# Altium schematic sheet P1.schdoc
size 297 x 209 mm; Symbol: Drawing-Symbol_A4; @Project Name: Assisant vocal; @Page Count: 1; @Update Date: 2026-05-29; @Create Date: 2026-02-14; @Schematic Name: Dessous; @Page No: 1; @Page Name: P1; Company: EasyEDA.com; Version: V1.0; Page Size: A4; @Create Time: 20:23:05; @Update Time: 12:29:57; Border: 1; Width: 1170; Height: 825; Region Start: 1; X Region Count: 6; Y Region Count: 4; Blade Width: 10; Title Block Position: 3; @Board Name: Dessous; Device: Drawing-Symbol_A4
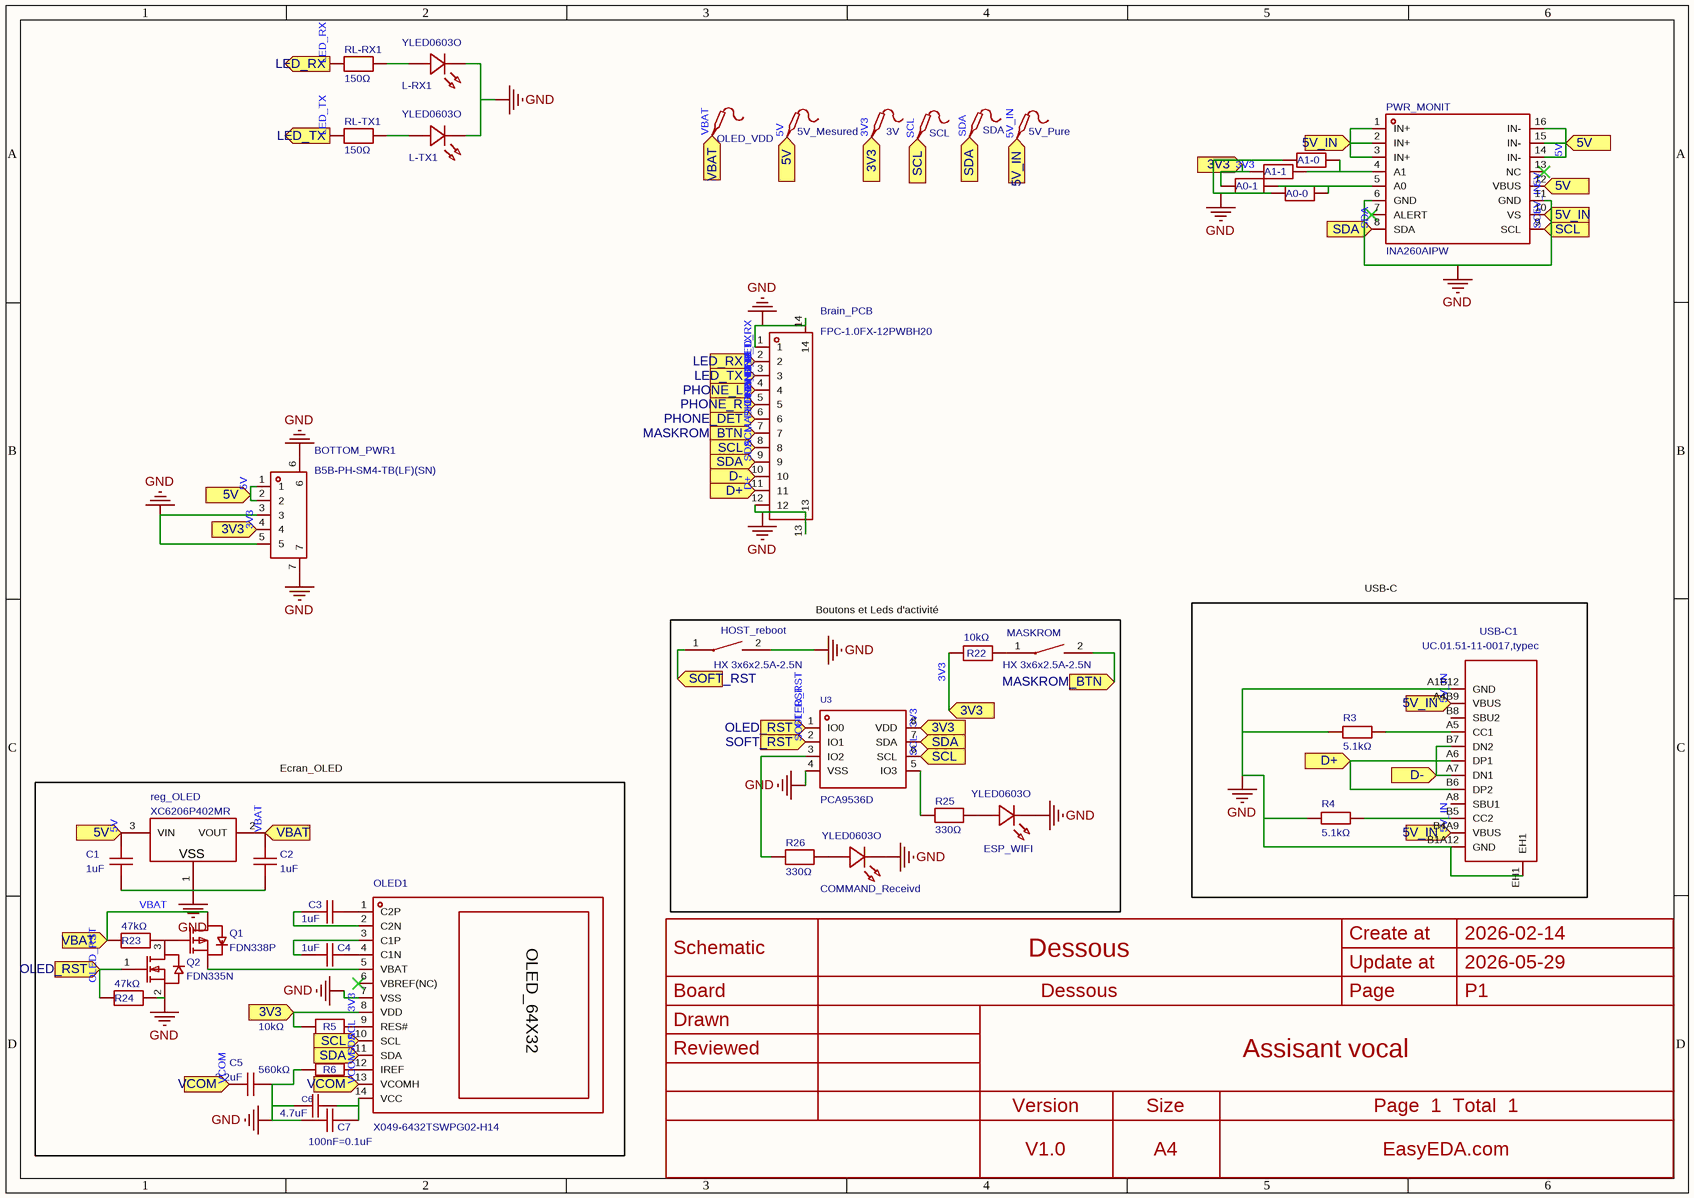
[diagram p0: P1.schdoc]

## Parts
3V  (no value)  [Test-Point-0.5mm]
5V_Mesured  (no value)  [Test-Point-0.5mm]
5V_Pure  (no value)  [Test-Point-0.5mm]
A0-0  0Ω  [R0402]  (value not drawn)
A0-1  0Ω  [R0402]  (value not drawn)
A1-0  0Ω  [R0402]  (value not drawn)
A1-1  0Ω  [R0402]  (value not drawn)
BOTTOM_PWR1  B5B-PH-SM4-TB(LF)(SN)  [CONN-SMD_5P-P2.00_B6B-PH-SM4-TB-LF-SN]
Brain_PCB  FPC-1.0FX-12PWBH20  [FPC-SMD_12P-P1.00_XUNPU_FPC-1.0FX-12PWBH20]
C1  1uF  [C0603]
C2  1uF  [C0603]
C3  1uF  [C0603]
C4  1uF  [C0603]
C5  2.2uF  [C0603]
C6  4.7uF  [C0603]
C7  100nF=0.1uF  [C0603]
COMMAND_Receivd  YLED0603O  [LED0603-FD]
ESP_WIFI  YLED0603O  [LED0603-FD]
HOST_reboot  HX 3x6x2.5A-2.5N  [SW-SMD_HX-TS-1101-C-W]
L-RX1  YLED0603O  [LED0603-FD]
L-TX1  YLED0603O  [LED0603-FD]
MASKROM  HX 3x6x2.5A-2.5N  [SW-SMD_HX-TS-1101-C-W]
OLED1  X049-6432TSWPG02-H14  [OLED-SMD_X049-6432TSWPG02-H14]
OLED_VDD  (no value)  [Test-Point-0.5mm]
PWR_MONIT  INA260AIPW  [TSSOP-16_L5.0-W4.4-P0.65-LS6.4-BL]
Q1  FDN338P  [SOT-23-3_L2.9-W1.3-P1.90-LS2.4-BR]
Q2  FDN335N  [SOT-23-3_L3.0-W1.7-P0.95-LS2.9-BR]
R3  5.1kΩ  [R0603_1]
R4  5.1kΩ  [R0603_1]
R5  10kΩ  [R0603]
R6  560kΩ  [R0603]
R22  10kΩ  [R0603]
R23  47kΩ  [R0603]
R24  47kΩ  [R0603]
R25  330Ω  [R0603]
R26  330Ω  [R0603]
reg_OLED  XC6206P402MR  [SOT-23-3_L2.9-W1.6-P1.90-LS2.8-BR]
RL-RX1  150Ω  [R0603]
RL-TX1  150Ω  [R0603]
SCL  (no value)  [Test-Point-0.5mm]
SDA  (no value)  [Test-Point-0.5mm]
U3  PCA9536D  [SOIC-8_L4.9-W3.9-P1.27-LS6.0-BL]
USB-C1  UC.01.51-11-0017,typec  [TYPE-C-SMD_UC.01.51-11-0017]

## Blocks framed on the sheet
Boutons et Leds d'activité: COMMAND_Receivd ESP_WIFI HOST_reboot MASKROM R22 R25 R26 U3
USB-C: R3 R4 USB-C1
Ecran_OLED: C1-C7 OLED1 Q1 Q2 R5 R6 R23 R24 reg_OLED

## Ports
3V3 (in), 5V (in), 5V_IN (in), D+ (in), D- (in), LED_RX (in), LED_RX (out), LED_TX (in), LED_TX (out), MASKROM_BTN (in), OLED_RST (in), PHONE_DET (in), PHONE_L (in), PHONE_R (in), SCL (in), SDA (in), SOFT_RST (in), VBAT (in), VCOM (in)

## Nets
GND: A0-0.2 A1-0.2 BOTTOM_PWR1.3 BOTTOM_PWR1.5 BOTTOM_PWR1.6 BOTTOM_PWR1.7 Brain_PCB.1 Brain_PCB.12 Brain_PCB.13 Brain_PCB.14 C1.1 C2.2 C5.2 C6.1 C7.1 COMMAND_Receivd.2(K) ESP_WIFI.2(K) HOST_reboot.2 L-RX1.2(K) L-TX1.2(K) OLED1.7(VSS) PWR_MONIT.6(GND) PWR_MONIT.11(GND) Q2.2(S) R3.1 R4.1 R6.1 R24.2 reg_OLED.1(VSS) U3.4(VSS) USB-C1.A1B12(GND) USB-C1.B1A12(GND) USB-C1.EH1
3V3: 3V.1 A0-1.2 A1-1.2 BOTTOM_PWR1.4 OLED1.8(VDD) R5.1 R22.2 U3.8(VDD) ; port 3V3
5V: 5V_Mesured.1 BOTTOM_PWR1.1 BOTTOM_PWR1.2 C1.2 PWR_MONIT.12(VBUS) PWR_MONIT.14(IN-) PWR_MONIT.15(IN-) PWR_MONIT.16(IN-) reg_OLED.3(VIN) ; port 5V
5V_IN: 5V_Pure.1 PWR_MONIT.1(IN+) PWR_MONIT.2(IN+) PWR_MONIT.3(IN+) PWR_MONIT.10(VS) USB-C1.A4B9(VBUS) USB-C1.B4A9(VBUS) ; port 5V_IN
D+: Brain_PCB.11 USB-C1.A6(DP1) USB-C1.B6(DP2) ; port D+
D-: Brain_PCB.10 USB-C1.A7(DN1) USB-C1.B7(DN2) ; port D-
LED_RX: Brain_PCB.2 RL-RX1.1 ; port LED_RX
LED_TX: Brain_PCB.3 RL-TX1.1 ; port LED_TX
MASKROM_BTN: Brain_PCB.7 MASKROM.2 ; port MASKROM_BTN
OLED_RST: Q2.1(G) R24.1 U3.1(IO0) ; port OLED_RST
PHONE_DET: Brain_PCB.6 ; port PHONE_DET
PHONE_L: Brain_PCB.4 ; port PHONE_L
PHONE_R: Brain_PCB.5 ; port PHONE_R
SCL: Brain_PCB.8 OLED1.10(SCL) PWR_MONIT.9(SCL) SCL.1 U3.6(SCL) ; port SCL
SDA: Brain_PCB.9 OLED1.11(SDA) PWR_MONIT.8(SDA) SDA.1 U3.7(SDA) ; port SDA
SOFT_RST: HOST_reboot.1 U3.2(IO1) ; port SOFT_RST
VBAT: C2.1 OLED_VDD.1 Q1.3(D) R23.1 reg_OLED.2(VOUT) ; port VBAT
VCOM: C5.1 OLED1.13(VCOMH) ; port VCOM
NetA0-0_1: A0-0.1 A0-1.1 PWR_MONIT.5(A0)
NetA1-0_1: A1-0.1 A1-1.1 PWR_MONIT.4(A1)
NetC3_1: C3.1 OLED1.1(C2P)
NetC3_2: C3.2 OLED1.2(C2N)
NetC4_1: C4.1 OLED1.4(C1N)
NetC4_2: C4.2 OLED1.3(C1P)
NetC6_2: C6.2 C7.2 OLED1.14(VCC)
NetCOMMAND_Receivd_1: COMMAND_Receivd.1(A) R26.2
NetESP_WIFI_1: ESP_WIFI.1(A) R25.2
NetL-RX1_1: L-RX1.1(A) RL-RX1.2
NetL-TX1_1: L-TX1.1(A) RL-TX1.2
NetMASKROM_1: MASKROM.1 R22.1
NetOLED1_5: OLED1.5(VBAT) Q1.2(S)
NetOLED1_9: OLED1.9(RES#) R5.2
NetOLED1_12: OLED1.12(IREF) R6.2
NetQ1_1: Q1.1(G) Q2.3(D) R23.2
NetR3_2: R3.2 USB-C1.A5(CC1)
NetR4_2: R4.2 USB-C1.B5(CC2)
NetR25_1: R25.1 U3.5(IO3)
NetR26_1: R26.1 U3.3(IO2)

Not connected (* = marked no-connect by the designer): OLED1 6(VBREF(NC))*; PWR_MONIT 7(ALERT)* 13(NC)*; USB-C1 A8(SBU1) B8(SBU2)

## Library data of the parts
3V 5V_Mesured 5V_Pure OLED_VDD SCL SDA = Test-Point: Test Point 测试点; AddInBom: yes
A0-0 A0-1 A1-0 A1-1 = FRC0402P000 TS: Type:Thick Film Resistor Resistance:0Ω Tolerance:±5% Tolerance:±5% Power(Watts):62.5mW Voltage-Supply(Max):50V Operating Temperature:-55℃~+155℃ Operating Temperature:-55℃~+155℃; Manufacturer: FOJAN(富捷); AddInBom: yes; ModelId: efdecb7dae4442949d28eecaf748420f; ModelName: R0402_L1.0-W0.5-H0.4; ModelTransform: 39.37,19.685,0,0,0,0,0,0,0; Tolerance: ±5%; Power(Watts): 62.5mW; Voltage-Supply(Max): 50V
BOTTOM_PWR1 = B5B-PH-SM4-TB(LF)(SN): Pins Structure:1x5P Pitch:2mm Mounting Type:Surface Mount,Vertical Reference Series:PH Number of Pins:5P Number of Rows:1 Number of PINs Per Row:5 Row Spacing:- Current Rating:2A Contact Material:Copper Alloy Contact Plating:Tin Operating Temperature:-25℃; Manufacturer: JST; AddInBom: yes; ModelId: 42661aa5dd484b92a752559c239d11dd; ModelTransform: 551.18,295.275,0,0,0,0,0,3.425,0; Pins Structure: 1x5P; Pitch: 2mm; Reference Series: PH; Number of PINs Per Row: 5; Current Rating: 2A; Voltage Rating: 100V; Plastic Material: PA; Flame Retardant Rating: UL94V-0; Supplementary Features: Auxiliary Solder Pin; Z-Height of the Board: 6.6mm; X-Length of Bottom Edge on Board (Spacing Line): 13.95mm; Y-Width of Bottom Edge on Board: 7mm
Brain_PCB = FPC-1.0FX-12PWBH20: Locking Feature:Hinged Lid Contact Type:Surface Mount Number of Contacts:12P Pitch:1mm Mounting Type:Bottom Contact FFC, FCB Thickness:0.3mm FFC, FCB Thickness:0.3mm Height Above Board:2mm Contact Material:Phosphor Bronze Contact Plating:Tin Operating Tem; Manufacturer: XUNPU(讯普); AddInBom: yes; ModelId: 695df043a7de448bbae1c867db17c273; ModelTransform: 665.7467,242.1255,0,0,0,0,0.003,-68.386,0; Number of Contacts: 12P; Pitch: 1mm; FFC, FCB Thickness: 0.3mm; Rated Voltage (Max): 50V; Current Rating (Max): 500mA
C1-C4 = CL10B105KB8NQNC: Capacitance:1uF Tolerance:±10% Tolerance:±10% Voltage Rating:50V Temperature Coefficient:X7R; Manufacturer: SAMSUNG(三星); AddInBom: yes; ModelId: 624118aa3cc7497086c383c2d72e0852; ModelName: C0603_L1.6-W0.8-H0.8; ModelTransform: 62.992,31.496,0,0,0,0,0,0,0; Tolerance: ±10%; Voltage Rating: 50V; Temperature Coefficient: X7R
C5 = CL10A225KO8NNNC: Capacitance:2.2uF Tolerance:±10% Tolerance:±10% Voltage Rating:16V Temperature Coefficient:X5R; Manufacturer: SAMSUNG(三星); AddInBom: yes; ModelId: 624118aa3cc7497086c383c2d72e0852; ModelName: C0603_L1.6-W0.8-H0.8; ModelTransform: 62.992,31.496,0,0,0,0,0,0,0; Tolerance: ±10%; Voltage Rating: 16V; Temperature Coefficient: X5R
C6 = CL10A475KP8NNNC: Capacitance:4.7uF Tolerance:±10% Tolerance:±10% Voltage Rating:10V Temperature Coefficient:X5R; Manufacturer: SAMSUNG(三星); AddInBom: yes; ModelId: 624118aa3cc7497086c383c2d72e0852; ModelName: C0603_L1.6-W0.8-H0.8; ModelTransform: 62.992,31.496,0,0,0,0,0,0,0; Tolerance: ±10%; Voltage Rating: 10V; Temperature Coefficient: X5R
C7 = CC0603KRX7R9BB104: Capacitance:100nF Tolerance:±10% Tolerance:±10% Voltage Rating:50V Temperature Coefficient:X7R; Manufacturer: YAGEO(国巨); AddInBom: yes; ModelId: 624118aa3cc7497086c383c2d72e0852; ModelName: C0603_L1.6-W0.8-H0.8; ModelTransform: 62.992,31.496,0,0,0,0,0,0,0; Tolerance: ±10%; Voltage Rating: 50V; Temperature Coefficient: X7R
COMMAND_Receivd ESP_WIFI L-RX1 L-TX1 = YLED0603O: Lamp Holder Type:-；- Illumination Color:Orange Voltage - Forward(Vf):1.8V~2.4V Voltage - Forward(Vf):1.8V~2.4V Power(Watts):- Forward Current:25mA Wavelength - Dominant:600nm~612nm Wavelength - Dominant:600nm~612nm Peak Wavelength:- Diode Configuration:Di; Manufacturer: YONGYUTAI(永裕泰); AddInBom: yes; ModelId: fde3ab7d2585474cbe7c93bfe55424d4; ModelName: LED0603_Inf; ModelTransform: 60,30,0,0,0,0,0,0,0; Lamp Holder Type: -；-; Illumination Color: Orange; Forward Current: 25mA; Diode Configuration: Discrete Diode; Luminous Intensity: 358mcd; Viewing Angle: 120°
HOST_reboot MASKROM = HX 3x6x2.5A-2.5N: Circuit:SPST Actuator Style:Square Button Operating Force:2.5N Mounting Type:Surface Mount,Vertical Length:6mm Width:3.6mm Switch Height:2.5mm with Bracket:Without Bracket Contact Current:50mA Voltage Rating:12V Actuator/Cap Color:White With Lamp:No IP Ra; Manufacturer: hanxia(韩下); Symbol: HX TS-1101-C-W; AddInBom: yes; ModelId: 5e1db8552bd8464f811de570386c8572; ModelTransform: 314.96,141.732,0,0,0,0,0,0,0; Circuit: SPST; Operating Force: 2.5N; Switch Height: 2.5mm; Contact Current: 50mA; Voltage Rating: 12V; Actuator/Cap Color: White; With Lamp: No; Life: 30,000 Cycles
OLED1 = X049-6432TSWPG02-H14: Manufacturer: Wisevision(新智景); AddInBom: yes; ModelId: efb5afee52124343b507ad011084a819; ModelTransform: 551.18,848.42346,0,0,0,0,0,385.828,0
PWR_MONIT = INA260AIPW: Vcm - Common Mode Voltage:0V~36V Vcm - Common Mode Voltage:0V~36V Ib - Input Bias Current:- Vos - Input Offset Voltage:- Operating Temperature:-40℃~+125℃ Operating Temperature:-40℃~+125℃; Manufacturer: TI(德州仪器); AddInBom: yes; ModelId: b0d79b97e3b34f0e897b079842b32384; ModelName: TSSOP-16_L5.0-W4.4-H1.0-LS6.4-P0.65; ModelTransform: 252.188,196.85,0,90,0,0,0,0.005,0; Vcm - Common Mode Voltage: 0V~36V
Q1 = FDN338P_C22363749: Number:1 P-Channel Drain to Source Voltage:20V Current - Continuous Drain(Id):2A RDS(on):82mΩ@4.5V Pd - Power Dissipation:800mW Gate Threshold Voltage (Vgs(th)):620mV Gate Charge(Qg):2.2nC@4.5V Input Capacitance(Ciss):185pF Reverse Transfer Capacitance (C; Manufacturer: ElecSuper(静芯); AddInBom: yes; ModelId: 62a57c6760504a01965db6419a6d07df; ModelName: SOT-23-3P_L2.9-W1.3-H1.0-LS2.4-P0.95; ModelTransform: 98.425,114.173,0,180,0,0,0.0005,-0.0005,0; Drain to Source Voltage: 20V; Current - Continuous Drain(Id): 2A; Pd - Power Dissipation: 800mW; Gate Threshold Voltage (Vgs(th)): 620mV; Input Capacitance(Ciss): 185pF; Reverse Transfer Capacitance (Crss@Vds): 25pF; Output Capacitance(Coss): 35pF
Q2 = FDN335N: Type:1 N-Channel Drain Source Voltage (Vdss): Continuous Drain Current (Id): Drain Source On Resistance (RDS(on)@Vgs,Id):0.07Ω@4.5V,1.7A Power Dissipation (Pd):500mW Gate Threshold Voltage (Vgs(th)@Id):1.5V@250uA Total Gate Charge (Qg@Vgs):3.5nC Input Cap; Manufacturer: onsemi(安森美); AddInBom: yes; ModelId: 4eed685bb9f4439b846746bc2193f3c0; ModelName: SOT-23-3L_L2.9-W1.6-H1.1-LS2.8-P0.95; ModelTransform: 114.173,110.236,0,90,0,0,0,0,0; Power Dissipation (Pd): 500mW; Total Gate Charge (Qg@Vgs): 3.5nC; Input Capacitance (Ciss@Vds): 310pF@10V; Reverse Transfer Capacitance (Crss@Vds): 40pF
R3 R4 = 0603WAF5101T5E: Type:Thick Film Resistor Resistance:5.1kΩ Tolerance:±1% Tolerance:±1% Power(Watts):100mW Voltage-Supply(Max):75V Temperature Coefficient:±100ppm/℃ Temperature Coefficient:±100ppm/℃ Operating Temperature:-55℃~+155℃ Operating Temperature:-55℃~+155℃; Manufacturer: UNI-ROYAL(厚声); AddInBom: yes; ModelId: 112863783b5b41f1b5254f87eedc7932; ModelName: R0603; ModelTransform: 31.8897,63.7794,0,90,0,0,0,0,0; Tolerance: ±1%; Power(Watts): 100mW; Voltage-Supply(Max): 75V
R5 R22 = FRC0603J103 TS: Type:Thick Film Resistor Resistance:10kΩ Tolerance:±5% Tolerance:±5% Power(Watts):100mW Voltage-Supply(Max):75V Temperature Coefficient:±100ppm/℃ Temperature Coefficient:±100ppm/℃ Operating Temperature:-55℃~+155℃ Operating Temperature:-55℃~+155℃; Manufacturer: FOJAN(富捷); AddInBom: yes; ModelId: 112863783b5b41f1b5254f87eedc7932; ModelTransform: 31.8897,63.7794,0,90,0,0,0,0,0; Tolerance: ±5%; Power(Watts): 100mW; Voltage-Supply(Max): 75V
R6 = RC0603FR-07560KL: Type:Thick Film Resistors Resistance: Tolerance:±1% Tolerance:±1% Power(Watts): Overload Voltage (Max): Temperature Coefficient:±100ppm/℃ Temperature Coefficient:±100ppm/℃ Operating Temperature Range:-55℃~+155℃ Operating Temperature Range:-55℃~+155℃; Manufacturer: YAGEO(国巨); AddInBom: yes; ModelId: 112863783b5b41f1b5254f87eedc7932; ModelTransform: 31.8897,63.7794,0,90,0,0,0,0,0; Tolerance: ±1%
R23 R24 = FRC0603F4702TS: Type:Thick Film Resistor Resistance:47kΩ Tolerance:±1% Tolerance:±1% Power(Watts):100mW Voltage-Supply(Max):75V Temperature Coefficient:±100ppm/℃ Temperature Coefficient:±100ppm/℃ Operating Temperature:-55℃~+155℃ Operating Temperature:-55℃~+155℃; Manufacturer: FOJAN(富捷); AddInBom: yes; ModelId: 112863783b5b41f1b5254f87eedc7932; ModelTransform: 31.8897,63.7794,0,90,0,0,0,0,0; Tolerance: ±1%; Power(Watts): 100mW; Voltage-Supply(Max): 75V
R25 R26 = FRC0603J331 TS: Type:Thick Film Resistor Resistance:330Ω Tolerance:±5% Tolerance:±5% Power(Watts):100mW Voltage-Supply(Max):75V Temperature Coefficient:±100ppm/℃ Temperature Coefficient:±100ppm/℃ Operating Temperature:-55℃~+155℃ Operating Temperature:-55℃~+155℃; Manufacturer: FOJAN(富捷); AddInBom: yes; ModelId: 112863783b5b41f1b5254f87eedc7932; ModelTransform: 31.8897,63.7794,0,90,0,0,0,0,0; Tolerance: ±5%; Power(Watts): 100mW; Voltage-Supply(Max): 75V
reg_OLED = XC6206P402MR: Output Type:Fixed Voltage - Supply:6V Output Voltage:4V Output Voltage:4V Output Current:200mA Power Supply Rejection Ratio (PSRR):- Voltage Dropout:680mV@(100mA) standby current:1uA Features:Over Current Protection Operating Temperature:-40℃~+85℃@(Ta) Op; Manufacturer: TOREX(特瑞仕); AddInBom: yes; ModelId: 4eed685bb9f4439b846746bc2193f3c0; ModelName: SOT-23-3L_L2.9-W1.6-H1.1-LS2.8-P0.95; ModelTransform: 114.173,110.236,0,90,0,0,0,0,0; Output Type: Fixed; Voltage - Supply: 6V; Output Voltage: 4V; Output Current: 200mA; standby current: 1uA; Output Configuration: Positive; Number of Outputs: 1
RL-RX1 RL-TX1 = FRC0603J151 TS: Type:Thick Film Resistor Resistance:150Ω Tolerance:±5% Tolerance:±5% Power(Watts):100mW Voltage-Supply(Max):75V Temperature Coefficient:±100ppm/℃ Temperature Coefficient:±100ppm/℃ Operating Temperature:-55℃~+155℃ Operating Temperature:-55℃~+155℃; Manufacturer: FOJAN(富捷); AddInBom: yes; ModelId: 112863783b5b41f1b5254f87eedc7932; ModelTransform: 31.8897,63.7794,0,90,0,0,0,0,0; Tolerance: ±5%; Power(Watts): 100mW; Voltage-Supply(Max): 75V
U3 = PCA9536D: Interface:I2C；SMBus Number of I/O:4 Interrupt Output:No Interrupt Output Output Type:- Voltage - Supply:2.3V~5.5V Voltage - Supply:2.3V~5.5V Current - Output Low(IOL):24mA Current - Output High(IOH):- Clock Frequency:400kHz Operating Temperature:-40℃~+85℃; Manufacturer: NXP(恩智浦); Symbol: PCA9536D_C129522; AddInBom: yes; ModelId: 2ec1ac1bf9bf4d09a988fcee15e6a02d; ModelName: SOIC-8_L4.9-W3.9-H1.7-LS6.0-P1.27; ModelTransform: 192.913,236.22,0,0,0,0,0,0,0; Number of I/O: 4; Current - Output Low(IOL): 24mA; Clock Frequency: 400kHz; Number of Supporting Devices: 1; Quiescent Current: 250nA; Output Logic Level - High: 4V
USB-C1 = UC.01.51-11-0017,typec: AddInBom: yes; ModelId: e0a9d83f704144a48dae8635b7823cc8; ModelTransform: 351.9678,266.1412,0,0,0,0,0,-31.493,-31.496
